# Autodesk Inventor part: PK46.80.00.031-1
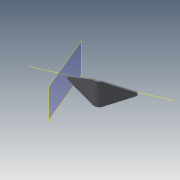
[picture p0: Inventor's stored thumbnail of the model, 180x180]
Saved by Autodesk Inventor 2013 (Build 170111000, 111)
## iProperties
Created: 2005-12
Part Number: PK46.80.00.031-1
Material: Steel, Mild
Document SubType Name: Листовой материал
Designer: SAlex
Manufacturer: Standard
Standards Organization: Custom
Density: 7.86 g/cm^3
Flat Pattern Width: 20.0383 cm
Flat Pattern Length: 20.0383 cm
Flat Pattern Area: 401.534 cm^2
Sheet Metal Rule: Default
Mass: 1079.17 g
Surface Area: 391.416 cm^2
Volume: 137.3 cm^3
Author: SAlex
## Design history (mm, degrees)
node "ФлнОтгиб1"
node "РабПлоскость1"
node "РабТочка1"
node "РабТочка2"
node "РабОсь1"
node "РабПлоскость2"
node "РабПлоскость3"
sketch "Эскиз4"
  geometry: L1 (141.716, 0)-(141.716, 150) reference; L2 (0, 150)-(141.716, 150) reference; L3 (0, 150)-(0, 0) reference; L4 (0, 0)-(141.716, 0) reference; L5 (141.716, 20.768)-(0, 75) reference; L6 (0, 75)-(141.716, 129.232) reference; 4 further points; 2 other entities
  constraints: 2 other
extrude "Выдавливание1" cut sketch "Эскиз4" stored distance "d11" = 10; taper "d12" = 0 deg
sketch "Эскиз5"
  geometry: L1 (141.716, 0)-(141.716, 150) reference; L2 (141.716, 150)-(0, 150) reference; L3 (0, 0)-(0, 150) reference; L4 (141.716, 0)-(0, 0) reference; L5 (0, 75)-(141.716, 129.232) reference; L6 (141.716, 20.768)-(0, 75) reference
extrude "Выдавливание2" cut sketch "Эскиз5" stored distance "d13" = 10; taper "d14" = 0 deg
node "РабПлоскость5"
sketch "Эскиз6"
  geometry: L1 (-127.655, 0)-(383.938, 0) reference; L2 (-37, -52.5)-(310.853, -52.5); L3 (310.853, -52.5)-(310.853, 52.5); L4 (310.853, 52.5)-(-37, 52.5); L5 (-37, 52.5)-(-37, -52.5)
  constraints: 8 end point, 2 parallel, 1 horizontal, 1 perpendicular
  dimensions: "d16" = 105 distance between parallel lines of L2 L4; "d17" = 52.5 distance between parallel lines of L1 L2 (= 0.5 x d16)
extrude "Выдавливание3" sketch "Эскиз6" stored distance "d18" = 10; taper "d19" = 0 deg
node "РабОсь2"
sketch "Эскиз7"
  geometry: L1 (0, 0)-(-137.189, -52.5) reference; L2 (-137.189, -52.5)-(0, -105) reference; L3 (4.527, -105)-(4.527, 0) reference; L4 (-122.189, -46.76)-(-122.189, -58.24)
  constraints: 2 end point, 2 point on line, 1 parallel
  dimensions: "d20" = 15 distance from line of L1.end L4
extrude "Выдавливание4" cut sketch "Эскиз7" stored distance "d21" = 10; taper "d22" = 0 deg
node "РабПлоскость6"
mirror "ЗеркОтобр1"
node "РабПлоскость7"
node "РабПлоскость8"
body "Solid1"
sketch "Эскиз2"
  geometry: L1 (146.236, -76.696)-(277.164, 0) reference; L2 (277.164, 0)-(280.225, -10.453) reference; L3 (280.225, -10.453)-(149.297, -87.149) reference; L4 (127.867, -87.149)-(-3.061, -10.453) reference; L5 (-3.061, -10.453)-(0, 0) reference; L6 (0, 0)-(130.928, -76.696) reference; 2 further points; 2 other entities
  constraints: 12 end point, 24 other
sketch "Эскиз3"
  geometry: L1 (130.928, 76.696)-(0, 0) reference; L2 (0, 0)-(-3.061, 10.453) reference; L3 (-3.061, 10.453)-(127.867, 87.149) reference; L4 (149.297, 87.149)-(280.225, 10.453) reference; L5 (280.225, 10.453)-(277.164, 0) reference; L6 (277.164, 0)-(146.236, 76.696) reference; 2 further points; 2 other entities
  constraints: 12 end point, 24 other
sketch "Эскиз1"
  geometry: L1 (-0.042, 0)-(149.958, 0); L2 (149.958, 0)-(256.024, 106.066)
  constraints: 4 end point, 1 equal length, 1 horizontal, 1 other
  dimensions: "d0" = 135 deg angle of L2 L1; "d1" = 150 distance of L1.start L1.end
feature "Плакирование1" dims "d2" = 150, "d3" = 8 (= BendReliefWidth), "d5" = 16 (= MinimumRemnant), "d7" = 20 (= BendRadius), "d8" = 8, "Thickness" = 8
feature "Изгиб1" dims "d3" = 8 (= BendReliefWidth), "d4" = 4 (= BendReliefDepth), "d5" = 16 (= MinimumRemnant), "d6" = 20 (= BendRadius), "d7" = 20 (= BendRadius), "d8" = 8, "SeamGap" = 0.01, "Thickness" = 8
node "Развертка"
feature "FlatPatternExtrusion2" dims "d0" = 8 (derived)
other parameters: "BendRadius" = 20, "BendReliefWidth" = 8 (= Thickness), "BendReliefDepth" = 4 (= 0.5 x Thickness), "CornerReliefSize" = 32 (= 4 x Thickness), "MinimumRemnant" = 16 (= 2 x Thickness), "d9" = 45 deg, "d10" = 90 deg, "d15" = 90 deg, "d23" = 90 deg, "d24" = 90 deg, "d25" = 90 deg, "JacobiRadiusSize" = 8 (= Thickness), "GapSize" = 8 (= Thickness)
